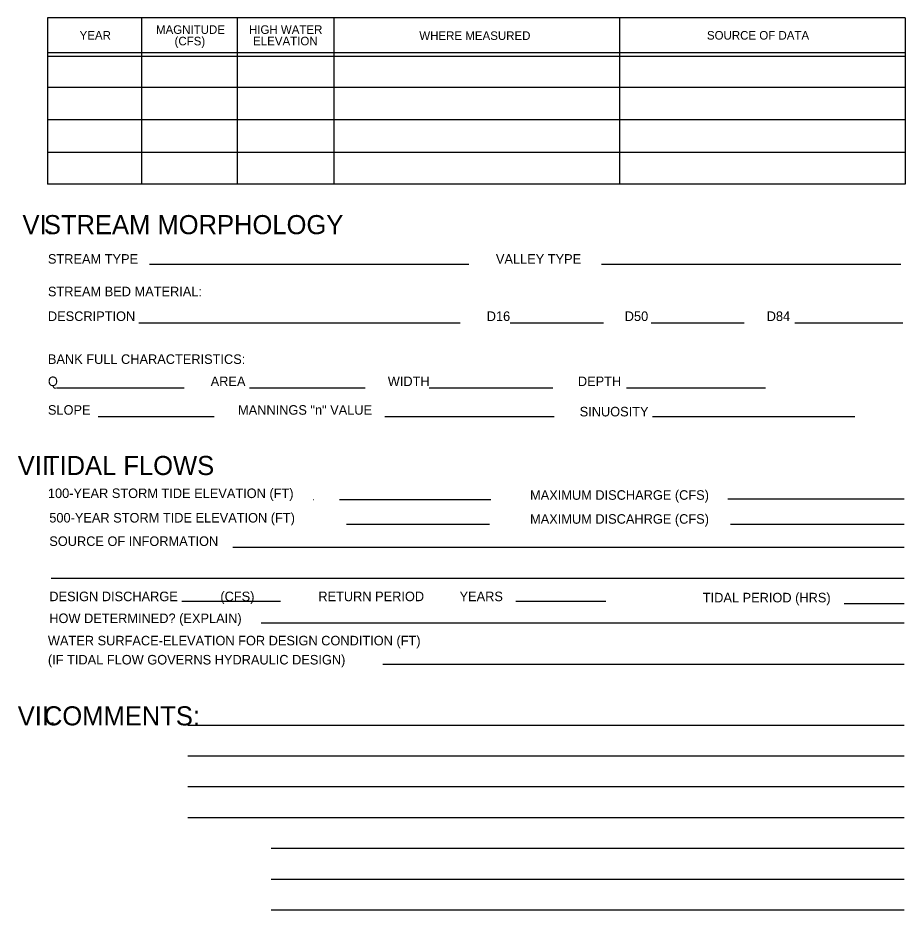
# Model space of a CAD drawing. Extents: x 2.9 to 32.9, y 0.8 to 21.2.
# Drawn here: x 2.89 to 12.03, y 1.97 to 11.17 of the extents above; entities that cross this region are included whole.
import ezdxf

# ---------------------------------------------------------------- set-up
doc = ezdxf.new("R2010")
doc.units = 0
doc.layers.add('ANNO-NOTE', color=7, linetype='Continuous')

msp = doc.modelspace()

# ---------------------------------------------------------------- linework, layer by layer
at = {"layer": 'ANNO-NOTE'}
for p, q in [((12.0308, 11.1674), (3.1952, 11.1674)), ((3.1952, 11.1674), (3.1952, 9.4544)), ((4.1622, 11.1674), (4.1622, 9.4544)), ((5.1507, 11.1674), (5.1507, 9.4544)), ((6.1444, 11.1674), (6.1444, 9.4544)), ((9.0876, 11.1674), (9.0876, 9.4544)), ((12.0308, 11.1674), (12.0308, 9.4544)), ((12.0308, 10.8073), (3.1952, 10.8073)), ((12.0308, 10.7678), (3.1952, 10.7678)), ((12.0308, 10.4496), (3.1952, 10.4496)), ((12.0308, 10.1152), (3.1952, 10.1152)), ((12.0308, 9.7807), (3.1952, 9.7807)), ((12.0308, 9.4544), (3.1952, 9.4544)), ((7.5354, 8.6238), (4.2454, 8.6238)), ((11.9848, 8.6238), (8.9033, 8.6238)), ((7.448, 8.0199), (4.138, 8.0199)), ((8.9235, 8.0199), (7.9611, 8.0199)), ((10.3723, 8.0199), (9.4132, 8.0199)), ((12.0056, 8.0199), (10.8955, 8.0199)), ((4.6042, 7.3489), (3.2896, 7.3489)), ((6.4687, 7.3489), (5.2749, 7.3489)), ((8.4004, 7.3489), (7.1261, 7.3489)), ((10.5912, 7.3489), (9.1616, 7.3489)), ((4.9127, 7.0537), (3.7188, 7.0537)), ((8.4138, 7.0537), (6.67, 7.0537)), ((11.5132, 7.0537), (9.4276, 7.0537)), ((5.9354, 6.1989), (5.9331, 6.1989)), ((7.7633, 6.1989), (6.205, 6.1989)), ((12.0218, 6.2078), (10.2047, 6.2078)), ((7.7499, 5.9465), (6.2762, 5.9465)), ((12.0218, 5.944), (10.2316, 5.944)), ((12.0218, 5.7071), (5.1041, 5.7071)), ((12.0218, 5.3896), (3.2324, 5.3896)), ((5.5947, 5.1515), (4.5793, 5.1515)), ((8.949, 5.1514), (8.0211, 5.1514)), ((12.0218, 5.1259), (11.4032, 5.1259)), ((12.0218, 4.9293), (5.3973, 4.9293)), ((12.0218, 4.5024), (6.6495, 4.5024)), ((12.0218, 3.8748), (4.6411, 3.8748)), ((12.0218, 3.5574), (4.6411, 3.5574)), ((12.0218, 3.24), (4.6411, 3.24)), ((12.0218, 2.9225), (4.6411, 2.9225)), ((12.0218, 2.6051), (5.4985, 2.6051)), ((12.0218, 2.2877), (5.4985, 2.2877)), ((12.0218, 1.9703), (5.4985, 1.9703))]:
    msp.add_line(p, q, dxfattribs=at)

# ---------------------------------------------------------------- texts
for s, height, p in [('MAGNITUDE', 0.08858, (4.3129, 11.002)), ('HIGH WATER', 0.08858, (5.2709, 11.002)), ('YEAR', 0.08858, (3.526, 10.943)), ('(CFS)', 0.08858, (4.5044, 10.8839)), ('ELEVATION', 0.08858, (5.3135, 10.8839)), ('WHERE MEASURED', 0.088583, (7.0257, 10.9394)), ('SOURCE OF DATA', 0.088583, (9.9887, 10.943)), ('VI. ', 0.19677, (2.9378, 8.9377)), ('STREAM MORPHOLOGY', 0.196772, (3.1583, 8.9377)), ('STREAM TYPE', 0.098425, (3.1998, 8.6333)), ('VALLEY TYPE', 0.098425, (7.815, 8.6333)), ('STREAM BED MATERIAL:', 0.098425, (3.1998, 8.2978)), ('DESCRIPTION', 0.098425, (3.1998, 8.0429)), ('D16', 0.09843, (7.7205, 8.0429)), ('D50', 0.09843, (9.1424, 8.0429)), ('D84', 0.09843, (10.6046, 8.0429)), ('BANK FULL CHARACTERISTICS:', 0.098425, (3.1998, 7.6001)), ('Q', 0.0984, (3.1998, 7.3719)), ('AREA', 0.09843, (4.8767, 7.3719)), ('WIDTH', 0.09843, (6.7011, 7.3719)), ('DEPTH', 0.09843, (8.6596, 7.3719)), ('SLOPE', 0.09843, (3.1998, 7.0767)), ('MANNINGS "n" VALUE', 0.098425, (5.1584, 7.0767)), ('SINUOSITY', 0.09843, (8.6778, 7.0594)), ('VII. ', 0.19677, (2.8889, 6.4551)), ('TIDAL FLOWS', 0.196772, (3.1583, 6.4551)), ('100-YEAR STORM TIDE ELEVATION (FT)', 0.098425, (3.1998, 6.2178)), ('MAXIMUM DISCHARGE (CFS)', 0.098425, (8.1669, 6.2)), ('500-YEAR STORM TIDE ELEVATION (FT)', 0.098425, (3.2139, 5.9654)), ('MAXIMUM DISCAHRGE (CFS)', 0.098425, (8.1669, 5.9531)), ('SOURCE OF INFORMATION', 0.098425, (3.2139, 5.7241)), ('DESIGN DISCHARGE            (CFS)                  RETURN PERIOD          YEARS              ', 0.098425, (3.2139, 5.1549)), ('TIDAL PERIOD (HRS)', 0.098425, (9.9467, 5.1425)), ('HOW DETERMINED? (EXPLAIN)      ', 0.098425, (3.2139, 4.9293)), ('WATER SURFACE-ELEVATION FOR DESIGN CONDITION (FT)', 0.098425, (3.1998, 4.6993)), ('(IF TIDAL FLOW GOVERNS HYDRAULIC DESIGN)', 0.098425, (3.1998, 4.5024)), ('VII. ', 0.19677, (2.8889, 3.8748)), ('COMMENTS:', 0.19677, (3.1583, 3.8748))]:
    msp.add_text(s, height=height, dxfattribs=at).set_placement(p)

doc.saveas('drawing.dxf')
